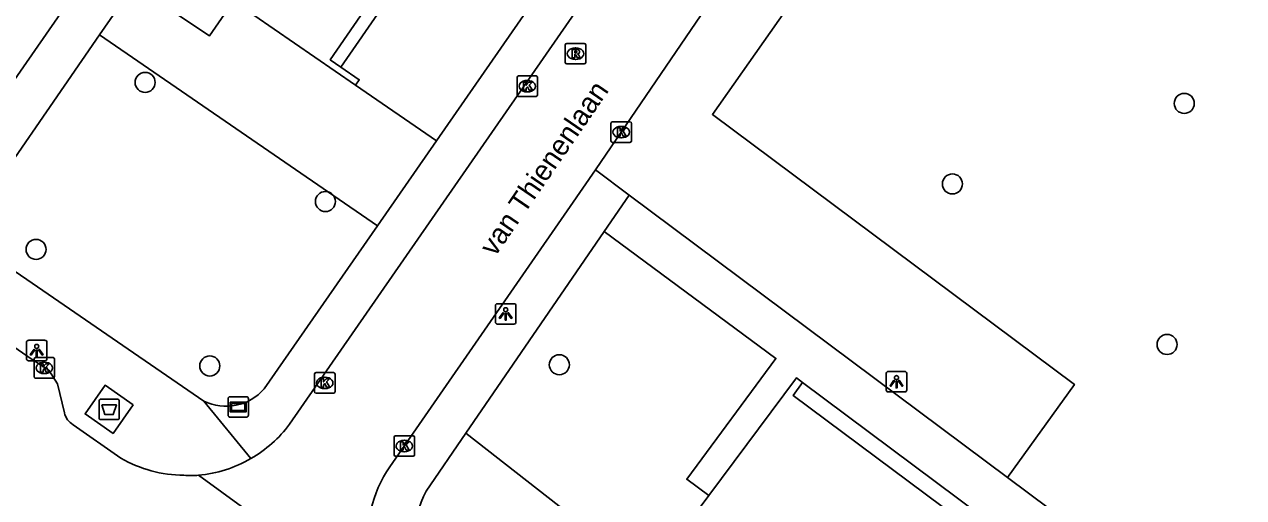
# Model space of a CAD drawing. Extents: x 160026 to 161302, y 384757 to 385701.
# Drawn here: x 160292 to 160351.5, y 385308.5 to 385331.6 of the extents above; entities that cross this region are included whole.
import ezdxf

# ---------------------------------------------------------------- set-up
doc = ezdxf.new("R2010")
doc.units = 0
for name, color, linetype in [('IMGEO_Afval_apart_plaats', 7, 'Continuous'), ('IMGEO_Boom', 7, 'Continuous'), ('IMGEO_Groenvoorziening', 7, 'Continuous'), ('IMGEO_Kolk', 7, 'Continuous'), ('IMGEO_Lichtpunt', 7, 'Continuous'), ('IMGEO_Openbare_ruimte_label', 7, 'Continuous'), ('IMGEO_Pand', 7, 'Continuous'), ('IMGEO_Rijbaan_lokaal_gesloten', 7, 'Continuous'), ('IMGEO_Rijbaan_lokaal_open', 7, 'Continuous'), ('IMGEO_Rioolput', 7, 'Continuous'), ('IMGEO_Straatnaambord', 7, 'Continuous'), ('IMGEO_Voetpad_gesloten', 7, 'Continuous'), ('IMGEO_Voetpad_open', 7, 'Continuous')]:
    doc.layers.add(name, color=color, linetype=linetype)

msp = doc.modelspace()

# ---------------------------------------------------------------- linework, layer by layer
at = {"layer": 'IMGEO_Afval_apart_plaats'}
for p, q in [((160295.639, 385312.427), (160295.639, 385313.227)), ((160295.639, 385313.227), (160295.639, 385312.427)), ((160295.739, 385313.327), (160296.529, 385313.327)), ((160296.529, 385313.327), (160295.739, 385313.327)), ((160296.629, 385313.227), (160296.629, 385312.427)), ((160296.629, 385312.427), (160296.629, 385313.227)), ((160296.529, 385312.327), (160295.739, 385312.327)), ((160295.739, 385312.327), (160296.529, 385312.327))]:
    msp.add_line(p, q, dxfattribs=at)
msp.add_lwpolyline([(160295.782, 385313.041), (160296.486, 385313.041), (160296.337, 385312.571), (160295.931, 385312.571), (160295.782, 385313.041)], dxfattribs=at)
for centre, start, end in [((160295.739, 385313.227), 90, 180), ((160295.739, 385313.227), 90, 180), ((160296.529, 385313.227), 0, 90), ((160296.529, 385313.227), 360, 90), ((160295.739, 385312.427), 180, 270), ((160295.739, 385312.427), 180, 270), ((160296.529, 385312.427), 270, 0), ((160296.529, 385312.427), 270, 0)]:
    msp.add_arc(centre, 0.1, start, end, dxfattribs=at)
at = {"layer": 'IMGEO_Boom'}
for centre in [(160297.889, 385328.777), (160348.596, 385327.751), (160337.282, 385323.823), (160306.688, 385322.966), (160292.566, 385320.631), (160347.757, 385315.994), (160318.102, 385315.004), (160301.045, 385314.944)]:
    msp.add_circle(centre, 0.489, dxfattribs=at)
at = {"layer": 'IMGEO_Groenvoorziening'}
for points in [[(160339.974, 385309.507), (160343.235, 385314.042), (160325.57, 385327.213), (160334.44, 385339.82)], [(160295.658, 385331.097), (160309.222, 385321.772)], [(160313.546, 385311.669), (160322.466, 385304.695)]]:
    msp.add_lwpolyline(points, dxfattribs=at)
at = {"layer": 'IMGEO_Kolk'}
for p, q in [((160316.04, 385328.165), (160316.04, 385329.017)), ((160316.115, 385329.091), (160316.967, 385329.091)), ((160316.528, 385328.871), (160316.553, 385328.871)), ((160317.041, 385329.017), (160317.041, 385328.165)), ((160316.967, 385328.091), (160316.115, 385328.091)), ((160316.551, 385328.311), (160316.526, 385328.311)), ((160320.695, 385326.852), (160321.547, 385326.852)), ((160320.62, 385325.926), (160320.62, 385326.778)), ((160321.108, 385326.632), (160321.133, 385326.632)), ((160321.621, 385326.778), (160321.621, 385325.926)), ((160321.547, 385325.852), (160320.695, 385325.852)), ((160321.131, 385326.072), (160321.106, 385326.072)), ((160292.469, 385314.424), (160292.469, 385315.276)), ((160292.544, 385315.35), (160293.396, 385315.35)), ((160292.957, 385315.13), (160292.982, 385315.13)), ((160293.47, 385315.276), (160293.47, 385314.424)), ((160293.396, 385314.35), (160292.544, 385314.35)), ((160292.98, 385314.57), (160292.955, 385314.57)), ((160306.155, 385313.692), (160306.155, 385314.544)), ((160306.23, 385314.618), (160307.082, 385314.618)), ((160306.643, 385314.398), (160306.668, 385314.398)), ((160307.156, 385314.544), (160307.156, 385313.692)), ((160306.666, 385313.838), (160306.641, 385313.838)), ((160307.082, 385313.618), (160306.23, 385313.618)), ((160310.035, 385310.615), (160310.035, 385311.467)), ((160310.11, 385311.541), (160310.962, 385311.541)), ((160310.523, 385311.321), (160310.548, 385311.321)), ((160311.036, 385311.467), (160311.036, 385310.615)), ((160310.546, 385310.761), (160310.521, 385310.761)), ((160310.962, 385310.541), (160310.11, 385310.541))]:
    msp.add_line(p, q, dxfattribs=at)
for points in [[(160316.04, 385328.165), (160316.04, 385329.017)], [(160316.115, 385329.091), (160316.967, 385329.091)], [(160316.361, 385328.791), (160316.484, 385328.791), (160316.484, 385328.64), (160316.614, 385328.791), (160316.778, 385328.791), (160316.632, 385328.64), (160316.785, 385328.391), (160316.633, 385328.391), (160316.548, 385328.555), (160316.484, 385328.488), (160316.484, 385328.391), (160316.361, 385328.391), (160316.361, 385328.791)], [(160317.041, 385329.017), (160317.041, 385328.165)], [(160316.967, 385328.091), (160316.115, 385328.091)], [(160320.695, 385326.852), (160321.547, 385326.852)], [(160320.62, 385325.926), (160320.62, 385326.778)], [(160320.941, 385326.552), (160321.064, 385326.552), (160321.064, 385326.401), (160321.194, 385326.552), (160321.358, 385326.552), (160321.212, 385326.401), (160321.365, 385326.152), (160321.213, 385326.152), (160321.128, 385326.316), (160321.064, 385326.249), (160321.064, 385326.152), (160320.941, 385326.152), (160320.941, 385326.552)], [(160321.621, 385326.778), (160321.621, 385325.926)], [(160321.547, 385325.852), (160320.695, 385325.852)], [(160292.469, 385314.424), (160292.469, 385315.276)], [(160292.544, 385315.35), (160293.396, 385315.35)], [(160292.79, 385315.05), (160292.913, 385315.05), (160292.913, 385314.899), (160293.043, 385315.05), (160293.207, 385315.05), (160293.061, 385314.899), (160293.214, 385314.65), (160293.062, 385314.65), (160292.977, 385314.814), (160292.913, 385314.747), (160292.913, 385314.65), (160292.79, 385314.65), (160292.79, 385315.05)], [(160293.47, 385315.276), (160293.47, 385314.424)], [(160293.396, 385314.35), (160292.544, 385314.35)], [(160306.155, 385313.692), (160306.155, 385314.544)], [(160306.23, 385314.618), (160307.082, 385314.618)], [(160306.476, 385314.318), (160306.599, 385314.318), (160306.599, 385314.167), (160306.729, 385314.318), (160306.893, 385314.318), (160306.747, 385314.167), (160306.9, 385313.918), (160306.748, 385313.918), (160306.663, 385314.082), (160306.599, 385314.015), (160306.599, 385313.918), (160306.476, 385313.918), (160306.476, 385314.318)], [(160307.156, 385314.544), (160307.156, 385313.692)], [(160307.082, 385313.618), (160306.23, 385313.618)], [(160310.035, 385310.615), (160310.035, 385311.467)], [(160310.11, 385311.541), (160310.962, 385311.541)], [(160311.036, 385311.467), (160311.036, 385310.615)], [(160310.356, 385311.241), (160310.479, 385311.241), (160310.479, 385311.09), (160310.609, 385311.241), (160310.773, 385311.241), (160310.627, 385311.09), (160310.78, 385310.841), (160310.628, 385310.841), (160310.543, 385311.005), (160310.479, 385310.938), (160310.479, 385310.841), (160310.356, 385310.841), (160310.356, 385311.241)], [(160310.962, 385310.541), (160310.11, 385310.541)]]:
    msp.add_lwpolyline(points, dxfattribs=at)
for centre, start, end in [((160316.117, 385329.015), 91.55205, 178.44795), ((160316.117, 385329.015), 91.55205, 178.44795), ((160316.965, 385329.015), 1.55205, 88.44795), ((160316.965, 385329.015), 1.55205, 88.44795), ((160316.117, 385328.167), 181.55205, 268.44795), ((160316.117, 385328.167), 181.55205, 268.44795), ((160316.965, 385328.167), 271.55205, 358.44795), ((160316.965, 385328.167), 271.55205, 358.44795), ((160320.697, 385326.776), 91.55205, 178.44795), ((160320.697, 385326.776), 91.55205, 178.44795), ((160321.545, 385326.776), 1.55205, 88.44795), ((160321.545, 385326.776), 1.55205, 88.44795), ((160320.697, 385325.928), 181.55205, 268.44795), ((160320.697, 385325.928), 181.55205, 268.44795), ((160321.545, 385325.928), 271.55205, 358.44795), ((160321.545, 385325.928), 271.55205, 358.44795), ((160292.546, 385315.274), 91.55205, 178.44795), ((160292.546, 385315.274), 91.55205, 178.44795), ((160293.394, 385315.274), 1.55205, 88.44795), ((160293.394, 385315.274), 1.55205, 88.44795), ((160292.546, 385314.426), 181.55205, 268.44795), ((160292.546, 385314.426), 181.55205, 268.44795), ((160293.394, 385314.426), 271.55205, 358.44795), ((160293.394, 385314.426), 271.55205, 358.44795), ((160306.232, 385314.542), 91.55205, 178.44795), ((160306.232, 385314.542), 91.55205, 178.44795), ((160307.08, 385314.542), 1.55205, 88.44795), ((160307.08, 385314.542), 1.55205, 88.44795), ((160306.232, 385313.694), 181.55205, 268.44795), ((160306.232, 385313.694), 181.55205, 268.44795), ((160307.08, 385313.694), 271.55205, 358.44795), ((160307.08, 385313.694), 271.55205, 358.44795), ((160310.112, 385311.465), 91.55205, 178.44795), ((160310.112, 385311.465), 91.55205, 178.44795), ((160310.96, 385311.465), 1.55205, 88.44795), ((160310.96, 385311.465), 1.55205, 88.44795), ((160310.112, 385310.617), 181.55205, 268.44795), ((160310.112, 385310.617), 181.55205, 268.44795), ((160310.96, 385310.617), 271.55205, 358.44795), ((160310.96, 385310.617), 271.55205, 358.44795)]:
    msp.add_arc(centre, 0.0765, start, end, dxfattribs=at)
for centre, major_axis, ratio, start_param, end_param in [((160316.527, 385328.591), (-0.387, 0.002), 0.722429, 4.712389, 7.853982), ((160316.552, 385328.591), (-0.39, 0.002), 0.717154, 1.570796, 4.712389), ((160321.107, 385326.352), (-0.387, 0.002), 0.722429, 4.712389, 7.853982), ((160321.132, 385326.352), (-0.39, 0.002), 0.717154, 1.570796, 4.712389), ((160292.956, 385314.85), (-0.387, 0.002), 0.722429, 4.712389, 7.853982), ((160292.981, 385314.85), (-0.39, 0.002), 0.717154, 1.570796, 4.712389), ((160306.642, 385314.118), (-0.387, 0.002), 0.722429, 4.712389, 7.853982), ((160306.667, 385314.118), (-0.39, 0.002), 0.717154, 1.570796, 4.712389), ((160310.522, 385311.041), (-0.387, 0.002), 0.722429, 4.712389, 7.853982), ((160310.547, 385311.041), (-0.39, 0.002), 0.717154, 1.570796, 4.712389)]:
    msp.add_ellipse(centre, major_axis=major_axis, ratio=ratio, start_param=start_param, end_param=end_param, dxfattribs=at)
at = {"layer": 'IMGEO_Lichtpunt'}
for p, q in [((160314.986, 385317.888), (160314.986, 385317.081)), ((160314.986, 385317.888), (160314.986, 385317.081)), ((160315.888, 385317.983), (160315.08, 385317.983)), ((160315.888, 385317.983), (160315.08, 385317.983)), ((160315.982, 385317.081), (160315.982, 385317.888)), ((160315.982, 385317.081), (160315.982, 385317.888)), ((160315.08, 385316.987), (160315.888, 385316.987)), ((160315.08, 385316.987), (160315.888, 385316.987)), ((160292.101, 385316.1), (160292.101, 385315.293)), ((160292.101, 385316.1), (160292.101, 385315.293)), ((160293.003, 385316.195), (160292.195, 385316.195)), ((160293.003, 385316.195), (160292.195, 385316.195)), ((160293.097, 385315.293), (160293.097, 385316.1)), ((160293.097, 385315.293), (160293.097, 385316.1)), ((160292.195, 385315.199), (160293.003, 385315.199)), ((160292.195, 385315.199), (160293.003, 385315.199)), ((160334.056, 385314.581), (160334.056, 385313.774)), ((160334.056, 385314.581), (160334.056, 385313.774)), ((160334.958, 385314.676), (160334.15, 385314.676)), ((160334.958, 385314.676), (160334.15, 385314.676)), ((160335.052, 385313.774), (160335.052, 385314.581)), ((160335.052, 385313.774), (160335.052, 385314.581)), ((160334.15, 385313.68), (160334.958, 385313.68)), ((160334.15, 385313.68), (160334.958, 385313.68))]:
    msp.add_line(p, q, dxfattribs=at)
for points in [[(160315.36, 385317.552), (160315.399, 385317.524), (160315.211, 385317.262), (160315.173, 385317.289), (160315.36, 385317.552)], [(160315.462, 385317.504), (160315.509, 385317.504), (160315.509, 385317.182), (160315.462, 385317.182), (160315.462, 385317.504)], [(160315.572, 385317.524), (160315.61, 385317.551), (160315.797, 385317.289), (160315.758, 385317.261), (160315.572, 385317.524)], [(160292.475, 385315.764), (160292.514, 385315.736), (160292.326, 385315.474), (160292.288, 385315.501), (160292.475, 385315.764)], [(160292.577, 385315.716), (160292.624, 385315.716), (160292.624, 385315.394), (160292.577, 385315.394), (160292.577, 385315.716)], [(160292.687, 385315.736), (160292.725, 385315.763), (160292.912, 385315.501), (160292.873, 385315.473), (160292.687, 385315.736)], [(160334.43, 385314.245), (160334.469, 385314.217), (160334.281, 385313.955), (160334.243, 385313.982), (160334.43, 385314.245)], [(160334.532, 385314.197), (160334.579, 385314.197), (160334.579, 385313.875), (160334.532, 385313.875), (160334.532, 385314.197)], [(160334.642, 385314.217), (160334.68, 385314.244), (160334.867, 385313.982), (160334.828, 385313.954), (160334.642, 385314.217)]]:
    msp.add_lwpolyline(points, dxfattribs=at)
for centre in [(160315.485, 385317.686), (160292.6, 385315.898), (160334.555, 385314.379)]:
    msp.add_circle(centre, 0.0994, dxfattribs=at)
for centre, start, end in [((160315.08, 385317.888), 90, 180), ((160315.08, 385317.888), 90, 180), ((160315.888, 385317.888), 0, 90), ((160315.888, 385317.888), 0, 90), ((160315.08, 385317.081), 180, 270), ((160315.08, 385317.081), 180, 270), ((160315.888, 385317.081), 270, 0), ((160315.888, 385317.081), 270, 360), ((160292.195, 385316.1), 90, 180), ((160292.195, 385316.1), 90, 180), ((160293.003, 385316.1), 0, 90), ((160293.003, 385316.1), 0, 90), ((160292.195, 385315.293), 180, 270), ((160292.195, 385315.293), 180, 270), ((160293.003, 385315.293), 270, 0), ((160293.003, 385315.293), 270, 360), ((160334.15, 385314.581), 90, 180), ((160334.15, 385314.581), 90, 180), ((160334.958, 385314.581), 0, 90), ((160334.958, 385314.581), 0, 90), ((160334.15, 385313.774), 180, 270), ((160334.15, 385313.774), 180, 270), ((160334.958, 385313.774), 270, 0), ((160334.958, 385313.774), 270, 360)]:
    msp.add_arc(centre, 0.0946, start, end, dxfattribs=at)
at = {"layer": 'IMGEO_Pand'}
for points in [[(160307.444, 385329.521), (160306.925, 385329.878), (160311.213, 385336.125)], [(160308.154, 385328.644), (160302.194, 385332.736)], [(160307.444, 385329.521), (160308.336, 385328.909), (160308.154, 385328.644)], [(160329.975, 385314.134), (160329.671, 385314.36), (160325.396, 385308.625)], [(160344.055, 385302.669), (160329.511, 385313.511), (160329.975, 385314.134)], [(160323.007, 385305.421), (160325.396, 385308.625)]]:
    msp.add_lwpolyline(points, dxfattribs=at)
at = {"layer": 'IMGEO_Rijbaan_lokaal_gesloten'}
for points in [[(160229.443, 385358.537), (160247.822, 385345.89), (160271.303, 385329.79), (160292.372, 385315.253), (160293.191, 385314.733), (160293.613, 385314.078), (160293.953, 385312.653)], [(160294.373, 385312.08), (160296.702, 385310.446)], [(160300.495, 385309.611), (160311.165, 385301.848)]]:
    msp.add_lwpolyline(points, dxfattribs=at)
for centre, radius, start, end in [((160294.842, 385312.864), 0.913, 193.35428, 239.12738), ((160299.832, 385315.909), 6.296, 240.18924, 269.55244), ((160300.157, 385315.944), 6.342, 266.62107, 273.05705)]:
    msp.add_arc(centre, radius, start, end, dxfattribs=at)
at = {"layer": 'IMGEO_Rijbaan_lokaal_open'}
for points in [[(160304.94, 385312.099), (160334.85, 385355.222)], [(160319.859, 385324.51), (160333.555, 385344.612)], [(160311.752, 385335.755), (160307.444, 385329.521)], [(160316.619, 385332.413), (160312.11, 385325.926)], [(160312.11, 385325.926), (160308.154, 385328.644)], [(160319.859, 385324.51), (160318.625, 385322.728), (160309.828, 385310.02)]]:
    msp.add_lwpolyline(points, dxfattribs=at)
for centre, radius, start, end in [((160299.896, 385315.895), 6.313, 299.964, 323.03548), ((160299.902, 385315.878), 6.295, 275.4039, 299.99262), ((160314.717, 385306.626), 5.952, 145.23597, 189.30563)]:
    msp.add_arc(centre, radius, start, end, dxfattribs=at)
at = {"layer": 'IMGEO_Rioolput'}
for p, q in [((160318.39, 385329.751), (160318.39, 385330.603)), ((160318.465, 385330.677), (160319.317, 385330.677)), ((160318.878, 385330.457), (160318.903, 385330.457)), ((160319.391, 385330.603), (160319.391, 385329.751)), ((160318.901, 385329.897), (160318.876, 385329.897)), ((160319.317, 385329.677), (160318.465, 385329.677))]:
    msp.add_line(p, q, dxfattribs=at)
for points in [[(160318.39, 385329.751), (160318.39, 385330.603)], [(160318.465, 385330.677), (160319.317, 385330.677)], [(160318.979, 385330.375), (160318.727, 385330.377), (160318.727, 385329.977)], [(160319.391, 385330.603), (160319.391, 385329.751)], [(160318.727, 385329.977), (160318.851, 385329.977), (160318.851, 385330.139), (160318.862, 385330.139)], [(160318.905, 385330.296), (160318.851, 385330.296), (160318.851, 385330.215)], [(160318.851, 385330.215), (160318.903, 385330.215)], [(160318.909, 385330.11), (160318.98, 385329.977), (160319.12, 385329.977), (160319.055, 385330.103)], [(160319.317, 385329.677), (160318.465, 385329.677)]]:
    msp.add_lwpolyline(points, dxfattribs=at)
for centre, radius, start, end in [((160318.467, 385330.601), 0.0765, 91.55205, 178.44795), ((160318.467, 385330.601), 0.0765, 91.55205, 178.44795), ((160318.978, 385330.265), 0.109, 350.36119, 89.41601), ((160319.315, 385330.601), 0.0765, 1.55205, 88.44795), ((160319.315, 385330.601), 0.0765, 1.55205, 88.44795), ((160318.861, 385330.086), 0.0533, 26.02933, 88.69889), ((160318.887, 385330.404), 0.19, 274.7715, 282.96867), ((160318.911, 385330.2), 0.0964, 77.00612, 93.18647), ((160318.925, 385330.257), 0.0378, 276.66336, 79.67722), ((160318.976, 385330.265), 0.112, 277.58423, 350.98172), ((160318.96, 385330.05), 0.108, 29.51342, 73.79051), ((160318.467, 385329.753), 0.0765, 181.55205, 268.44795), ((160318.467, 385329.753), 0.0765, 181.55205, 268.44795), ((160319.315, 385329.753), 0.0765, 271.55205, 358.44795), ((160319.315, 385329.753), 0.0765, 271.55205, 358.44795)]:
    msp.add_arc(centre, radius, start, end, dxfattribs=at)
for centre, major_axis, ratio, start_param, end_param in [((160318.877, 385330.177), (-0.387, 0.002), 0.722429, 4.712389, 7.853982), ((160318.902, 385330.177), (-0.39, 0.002), 0.717154, 1.570796, 4.712389)]:
    msp.add_ellipse(centre, major_axis=major_axis, ratio=ratio, start_param=start_param, end_param=end_param, dxfattribs=at)
at = {"layer": 'IMGEO_Straatnaambord'}
for p, q in [((160301.937, 385312.546), (160301.937, 385313.346)), ((160301.937, 385313.346), (160301.937, 385312.546)), ((160302.037, 385313.446), (160302.827, 385313.446)), ((160302.827, 385313.446), (160302.037, 385313.446)), ((160302.927, 385313.346), (160302.927, 385312.546)), ((160302.927, 385312.546), (160302.927, 385313.346)), ((160302.827, 385312.446), (160302.037, 385312.446)), ((160302.037, 385312.446), (160302.827, 385312.446))]:
    msp.add_line(p, q, dxfattribs=at)
for points in [[(160302.038, 385313.178), (160302.826, 385313.178), (160302.826, 385312.714), (160302.038, 385312.714), (160302.038, 385313.178)], [(160302.103, 385313.113), (160302.103, 385312.779), (160302.761, 385312.779), (160302.761, 385313.113), (160302.103, 385313.113)]]:
    msp.add_lwpolyline(points, dxfattribs=at)
for centre, start, end in [((160302.037, 385313.346), 90, 180), ((160302.037, 385313.346), 90, 180), ((160302.827, 385313.346), 0, 90), ((160302.827, 385313.346), 360, 90), ((160302.037, 385312.546), 180, 270), ((160302.037, 385312.546), 180, 270), ((160302.827, 385312.546), 270, 0), ((160302.827, 385312.546), 270, 0)]:
    msp.add_arc(centre, 0.1, start, end, dxfattribs=at)
at = {"layer": 'IMGEO_Voetpad_gesloten'}
msp.add_lwpolyline([(160297.304, 385313.049), (160296.33, 385311.651), (160294.963, 385312.604), (160295.937, 385314.002), (160297.304, 385313.049)], dxfattribs=at)
at = {"layer": 'IMGEO_Voetpad_open'}
for points in [[(160290.042, 385337.923), (160291.635, 385336.821), (160293.982, 385340.246), (160297.628, 385337.723), (160290.126, 385326.94)], [(160302.194, 385332.736), (160301.031, 385331.055), (160297.333, 385333.526), (160295.658, 385331.097)], [(160295.658, 385331.097), (160288.926, 385321.336)], [(160312.11, 385325.926), (160309.222, 385321.772)], [(160321.516, 385323.274), (160319.859, 385324.51)], [(160320.296, 385321.498), (160321.516, 385323.274)], [(160339.974, 385309.507), (160321.516, 385323.274)], [(160309.222, 385321.772), (160303.699, 385313.827)], [(160313.546, 385311.669), (160320.296, 385321.498)], [(160325.396, 385308.625), (160324.315, 385309.421), (160328.67, 385315.311), (160320.296, 385321.498)], [(160300.756, 385313.228), (160288.926, 385321.336)], [(160388.692, 385270.335), (160329.975, 385314.134)], [(160300.756, 385313.228), (160303.049, 385310.426)], [(160311.604, 385308.842), (160313.546, 385311.669)], [(160394.21, 385269.049), (160339.974, 385309.507)]]:
    msp.add_lwpolyline(points, dxfattribs=at)
for centre, radius, start, end in [((160301.838, 385315.441), 2.463, 243.94401, 319.06496), ((160314.625, 385307.107), 3.484, 150.13234, 226.13542)]:
    msp.add_arc(centre, radius, start, end, dxfattribs=at)

# ---------------------------------------------------------------- texts
at = {"layer": 'IMGEO_Openbare_ruimte_label'}
msp.add_text('van Thienenlaan', height=1, rotation=55.59477, dxfattribs=at).set_placement((160314.963, 385320.236))

doc.saveas('drawing.dxf')
